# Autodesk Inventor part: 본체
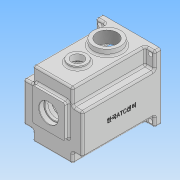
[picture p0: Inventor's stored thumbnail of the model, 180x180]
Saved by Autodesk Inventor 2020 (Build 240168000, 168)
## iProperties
Created: 2022-01
Part Number: 본체
Material: 일반
Document SubType Name: Modeling
Designer: user
Density: 1 g/cm^3
Appearance: 기본값
Author: user
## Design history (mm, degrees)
sketch "스케치1"
  geometry: L1 (-49, 55)-(49, 55); L2 (49, 55)-(49, -55); L3 (49, -55)-(-49, -55); L4 (-49, -55)-(-49, 55); L5 (-49, 55)-(49, -55); L6 (49, 55)-(-49, -55); 1 further point
  constraints: 12 end point, 2 midpoint, 2 parallel, 1 horizontal, 1 perpendicular
  dimensions: "d0" = 98 distance of L1.start L1.end; "d1" = 110 distance of L3.end L1.start
extrude "돌출1" new body sketch "스케치1" distance "d2" = 130; taper "d3" = 0 deg
sketch "스케치2"
  geometry: L1 (49, 55)-(-49, 55) reference; L2 (-49, 55)-(-49, -55) reference; L3 (-49, -55)-(49, -55) reference; L4 (49, -55)-(49, 55) reference; L5 (-49, 55)-(-33, 55); L6 (-33, 55)-(-33, 28); L7 (-33, 28)-(-49, 28); L8 (-49, 28)-(-49, 55); L9 (49, 55)-(-49, 55) reference; L10 (0, 55)-(0, 0); L11 (0, 0)-(49, 0); L12 (49, -55)-(49, 55) reference; L13 (49, 55)-(33, 55); L14 (33, 55)-(33, 28); L15 (33, 28)-(49, 28); L16 (49, 28)-(49, 55); L17 (-49, 55)-(-49, -55) reference; L18 (-49, -55)-(-33, -55); L19 (-33, -55)-(-33, -38); L20 (-33, -38)-(-49, -38); L21 (-49, -38)-(-49, -55); L22 (49, -55)-(33, -55); L23 (33, -55)-(33, -38); L24 (33, -38)-(49, -38); L25 (49, -38)-(49, -55); 8 further points
  constraints: 36 end point, 6 parallel, 3 horizontal, 3 perpendicular, 3 symmetric about line, 2 midpoint, 1 vertical
  dimensions: "d4" = 16 distance of L1.end L5.end; "d5" = 27 distance of L5.end L6.end; "d6" = 16 distance of L19.end L20.end; "d7" = 16 distance of L23.end L24.end; "d8" = 17 distance of L18.end L19.end; "d9" = 17 distance of L22.end L23.end
extrude "돌출2" cut sketch "스케치2" distance "d10" = 120; taper "d11" = 0 deg
node "작업 평면1"
sketch "스케치4"
  geometry: L1 (98, 0)-(0, 0) reference; C1 r 22.5 at (49, -40); 1 further point
  constraints: 1 centre point, 1 vertical alignment
  dimensions: "d17" = 45 diameter of C1; "d19" = 40 distance from line of C1.centre L1
extrude "돌출4" join sketch "스케치4" stored distance "d21" = 7; taper "d22" = 0 deg
node "작업 평면2"
sketch "스케치5"
  geometry: C1 r 15 at (49, -89); C2 r 22.5 at (49, -40) reference; 1 further point
  constraints: 1 centre point, 1 vertical alignment
  dimensions: "d24" = 30 diameter of C1; "d25" = 49 distance of C1.centre C2.centre
extrude "돌출5" join sketch "스케치5" stored distance "d26" = 7; taper "d27" = 0 deg
sketch "스케치6"
  geometry: L1 (-49, 55)-(49, 55) reference; L2 (49, -55)-(-49, -55) reference; L3 (-23, 45)-(23, 45); L4 (23, 45)-(23, -5); L5 (23, -5)-(-23, -5); L6 (-23, -5)-(-23, 45); C1 r 42 at (0, -5); 6 further points
  constraints: 8 end point, 3 midpoint, 2 parallel, 2 vertical alignment, 1 centre point, 1 coincident, 1 horizontal, 1 perpendicular
  dimensions: "d28" = 50 distance from line of C1.centre L2; "d29" = 84 diameter of C1; "d30" = 50 distance from line of L3 C1.centre; "d31" = 46 distance of L3.start L3.end
extrude "돌출6" cut sketch "스케치6" distance "d32" = 121; taper "d33" = 0 deg
sketch "스케치7"
  geometry: L1 (23, 45)-(23, 30.143) reference; L2 (-23, 45)-(23, 45) reference; L3 (-23, 30.143)-(-23, 45) reference; L4 (26, 48)-(26, 31.729); L5 (-26, 31.729)-(-26, 48); L6 (-26, 48)-(26, 48); A1 r 42 centre (0, -5) between (-23, 30.143) and (23, 30.143) reference; A2 r 45 centre (0, -5) between (-26, 31.729) and (26, 31.729)
  constraints: 6 end point, 2 point on circle, 1 centre point, 3 other
  dimensions: "d38" = 3 distance between parallel lines of L2 L6
extrude "돌출7" cut sketch "스케치7" distance "d39" = 9; taper "d40" = 0 deg
sketch "스케치8"
  geometry: L1 (-27, 33)-(27, 33); L2 (27, 33)-(27, -21); L3 (27, -21)-(-27, -21); L4 (-27, -21)-(-27, 33); L5 (-27, 33)-(27, -21); L6 (27, 33)-(-27, -21); L7 (-33, -55)-(33, -55) reference; 3 further points
  constraints: 12 end point, 3 midpoint, 2 parallel, 1 horizontal, 1 perpendicular, 1 vertical alignment
  dimensions: "d41" = 54 distance of L2.end L3.end; "d42" = 54 distance of L1.end L2.end; "d43" = 61 distance from line of L7 point (0, 6)
extrude "돌출8" join sketch "스케치8" distance "d44" = 7; taper "d45" = 0 deg
sketch "스케치9"
  geometry: C1 r 22.5 at (0, 0) reference; 2 further points
  constraints: 1 coincident
hole "구멍1" sketch "스케치9" at (0, 0) diameter "d46" = 33.376; stored, may be unused: countersink angle "d50" = 90 deg, drill point angle "d52" = 118 deg; dims "d47" = 58, "d48" = 4, "d49" = 2, "d51" = 67.55
sketch "스케치10"
  geometry: C1 r 15 at (0, 0) reference; 2 further points
  constraints: 1 coincident
hole "구멍2" sketch "스케치10" at (0, 0) diameter "d53" = 20; stored, may be unused: countersink angle "d57" = 90 deg, drill point angle "d59" = 0 deg; dims "d54" = 58, "d55" = 4, "d56" = 2, "d58" = 63.3
sketch "스케치11"
  geometry: L1 (56, 9)-(56, -111) reference; L2 (56, -111)-(72, -111) reference; L3 (72, -121)-(72, -111) reference; L4 (72, -121)-(-26, -121) reference; L5 (-26, -121)-(-26, -111) reference; L6 (-26, -111)-(-10, -111) reference; L7 (-10, -111)-(-10, 9) reference; L8 (56, 9)-(-10, 9) reference; C1 r 15 at (23, -32) reference; C2 r 22.5 at (23, -81) reference; C3 r 15 at (23, -32); 1 further point
  constraints: 1 centre point, 1 coincident
  dimensions: "d60" = 30 diameter of C3
extrude "돌출9" cut sketch "스케치11" distance "d61" = 5; taper "d62" = 0 deg
sketch "스케치14"
  geometry: L1 (-33, 55)-(33, 55) reference; L2 (33, -55)-(-33, -55) reference; C1 r 21 at (0, 6); C2 r 15 at (0, -25); 4 further points
  constraints: 2 centre point, 2 vertical alignment, 1 midpoint
  dimensions: "d73" = 42 diameter of C1; "d74" = 61 distance from line of C1.centre L2; "d75" = 30 diameter of C2; "d76" = 31 distance of C2.centre C1.centre
extrude "돌출11" join sketch "스케치14" distance "d78" = 7; taper "d79" = 0 deg
sketch "스케치15"
  geometry: A1 r 15 centre (0, -25) between (-8.978, -12.984) and (8.978, -12.984) reference; A2 r 21 centre (0, 6) between (8.978, -12.984) and (-8.978, -12.984) reference; 1 further point
hole "구멍4" sketch "스케치15" at (0, 6) diameter "d80" = 28; stored, may be unused: countersink angle "d84" = 90 deg, drill point angle "d86" = 0 deg; dims "d81" = 58, "d82" = 35, "d83" = 10, "d85" = 20
sketch "스케치16"
  geometry: C1 r 14 at (0, 6) reference; 1 further point
hole "구멍5" sketch "스케치16" at (0, 6) diameter "d87" = 32; stored, may be unused: countersink angle "d91" = 90 deg, drill point angle "d93" = 0 deg; dims "d88" = 58, "d89" = 35, "d90" = 10, "d92" = 8.3
sketch "스케치17"
  geometry: C1 r 17.5 at (0, 6) reference; A1 r 15 centre (0, -25) between (-8.978, -12.984) and (8.978, -12.984) reference; A2 r 21 centre (0, 6) between (8.978, -12.984) and (-8.978, -12.984) reference; 1 further point
hole "구멍6" sketch "스케치17" at (0, -25) diameter "d94" = 19; stored, may be unused: countersink angle "d98" = 90 deg, drill point angle "d100" = 0 deg; dims "d95" = 58, "d96" = 22, "d97" = 7, "d99" = 10
sketch "스케치18"
  geometry: L1 (-36, -5)-(36, -5); L2 (-36, -9)-(-41.809, -9); L3 (-35.778, -1.006)-(-41.81, -1.006); L4 (35.778, -1.006)-(41.81, -1.006); L5 (35.778, -8.994)-(41.81, -8.994); A1 r 42 centre (0, -5) between (-23, 30.143) and (23, 30.143) reference; A2 r 36 centre (0, -5) between (-36, -5) and (36, -5); A3 r 4 centre (-36, -5) between (-36, -9) and (-35.778, -1.006); A4 r 4 centre (36, -5) between (35.778, -1.006) and (35.778, -8.994); 5 further points
  constraints: 13 point on circle, 10 end point, 5 horizontal, 4 coincident, 3 centre point, 1 midpoint, 1 tangent
  dimensions: "d101" = 72 diameter of A2; "d102" = 8 diameter of A3; "d103" = 8 diameter of A4
extrude "돌출12" join sketch "스케치18" stored distance "d104" = 7; taper "d105" = 0 deg
sketch "스케치20"
  geometry: A1 r 4 centre (-36, -5) between (-36, -9) and (-36.222, -1.006) reference; A2 r 4 centre (36, -5) between (36.222, -1.006) and (36.222, -8.994) reference; 3 further points
  constraints: 2 coincident
hole "구멍7" sketch "스케치20" at (-36, -5), (36, -5) diameter "d106" = 3.242; stored, may be unused: countersink angle "d110" = 90 deg, drill point angle "d112" = 118 deg; dims "d107" = 7, "d108" = 22, "d109" = 7, "d111" = 9
fillet "모깎기1" dims "d113" = 3
fillet "모깎기2" dims "d114" = 3
fillet "모깎기3" dims "d115" = 3
fillet "모깎기4" dims "d116" = 3
fillet "모깎기5" dims "d117" = 3
fillet "모깎기6" dims "d118" = 3
fillet "모깎기7" dims "d119" = 3
fillet "모깎기8" dims "d120" = 3
fillet "모깎기9" dims "d124" = 0.3
fillet "모깎기10" dims "d125" = 3
fillet "모깎기11" dims "d129" = 6
fillet "모깎기12" dims "d130" = 3
fillet "모깎기13" dims "d134" = 3
fillet "모깎기14" dims "d135" = 3
fillet "모깎기15" dims "d136" = 3
fillet "모깎기16" dims "d137" = 3
fillet "모깎기17" dims "d138" = 3
chamfer "모따기4" distance "d139" = 1; stored, may be unused: second distance "d140" = 2, angle "d141" = 30 deg
chamfer "모따기5" distance "d142" = 1; stored, may be unused: second distance "d143" = 2, angle "d144" = 30 deg
sketch "스케치21" dims "d154" = 10
  geometry: L1 (-49, -52)-(-49, 52) reference; L2 (-46, 55)-(46, 55) reference; 5 further points
  constraints: 1 horizontal, 2 other
  dimensions: "d145" = 7 distance from line of point (-42, 48) L1; "d146" = 7 distance from line of point (-42, 48) L2; "d147" = 7 distance from line of point (-42, -48) L1; "d148" = 96 distance of point (-42, -48) point (-42, 48); "d151" = 84 distance of point (-42, 48) point (42, 48)
hole "구멍8" sketch "스케치21" at (-42, 48), (-42, -48), (42, 48), (42, -48) diameter "d156" = 7; stored, may be unused: countersink angle "d160" = 90 deg, drill point angle "d162" = 0 deg; dims "d157" = 8, "d158" = 22, "d159" = 7, "d161" = 10
sketch "스케치22"
  geometry: L1 (-3, 87)-(-3, 66) reference; L2 (114, 90)-(0, 90) reference; L3 (114, 63)-(0, 63) reference; 2 further points
  constraints: 1 other
  dimensions: "d163" = 65 distance from line of point (62, 30) L1; "d165" = 27 distance between parallel lines of L3 L2 (derived); "d166" = 33 distance from line of point (62, 30) L3
feature "엠보싱1" sketch "스케치22" dims "d4" = 16, "d5" = 27, "d167" = 0.5, "d168" = 0
fillet "모깎기18" dims "d169" = 6
chamfer "모따기6" distance "d170" = 1; stored, may be unused: second distance "d171" = 2, angle "d172" = 30 deg
fillet "모깎기20" dims "d174" = 0.3
chamfer "모따기8" distance "d178" = 0.8; stored, may be unused: second distance "d179" = 2, angle "d180" = 30 deg
node "솔리드1"
node "투영된 루프1"
node "투영된 루프2"
node "투영된 루프3"
node "투영된 루프4"
node "투영된 루프7"
node "투영된 루프8"
feature "A9D066F2-1C7D-4E18-AEED-F7BC21143FA4" dims "d53" = 20, "d54" = 58, "d55" = 4, "d56" = 2, "d57" = 90 deg, "d58" = 63.3, "d59" = 0
other parameters: "d23" = 5
